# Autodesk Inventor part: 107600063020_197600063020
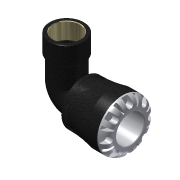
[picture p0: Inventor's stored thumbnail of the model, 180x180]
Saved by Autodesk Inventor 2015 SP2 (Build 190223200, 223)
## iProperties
Created: 2016-12
Part Number: 107600063020_197600063020
Material: PVC-Piping
Description: PLASSON 90° ELBOW WITH FEMALE INTEGRAL BRASS 63X2" SERIES 1
Document SubType Name: Modeling
Designer: KIM
Mass: 664.223 g
Surface Area: 733.008 cm^2
Volume: 474.445 cm^3
Density: 1.4 g/cm^3
Appearance: Black Cast
Author: KIM
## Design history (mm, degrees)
derived "1076.ipt"
feature "Solid1::1076.ipt"
tag "TaggingFeature1"
body "Solid1"
other parameters: "d1" = 37.8, "d2" = 63, "d3" = 78.75, "d4" = 103, "d8" = 90.64, "d13" = 9.7, "d14" = 9.7, "d15" = 0, "d17" = 360 deg, "d19" = 8 deg, "d20" = 1.26, "d21" = 1.26, "d22" = 8 deg, "d24" = 0, "d26" = 360 deg, "d33" = 10.3, "d51" = 1.03, "d54" = 22.05, "d55" = 13.86, "d57" = 19.012, "d58" = 0, "d74" = 0, "d82" = 1.26, "d115" = 360 deg, "d207" = 90 deg, "d228" = 18.7425, "d248" = 5.4, "d270" = 143, "d279" = 82, "d281" = 8.4984, "d294" = 56.656, "d295" = 26, "d296" = 28.6, "d297" = 50.9904, "d299" = 66.28752, "d300" = 50.9904, "d301" = 0, "d302" = 0, "d306" = 3.68264, "d309" = 90.9, "d310" = 12.17624, "d312" = 15 deg, "d313" = 0.824, "d314" = 10.26, "d315" = 0.515, "d_" = 63, "E_" = 103, "A_" = 143, "A_1" = 82, "l_2" = 26, "Rp_" = 56.656, "d9" = 12.125, "d11" = 103, "d12" = 78.75, "d298" = 73.6528
